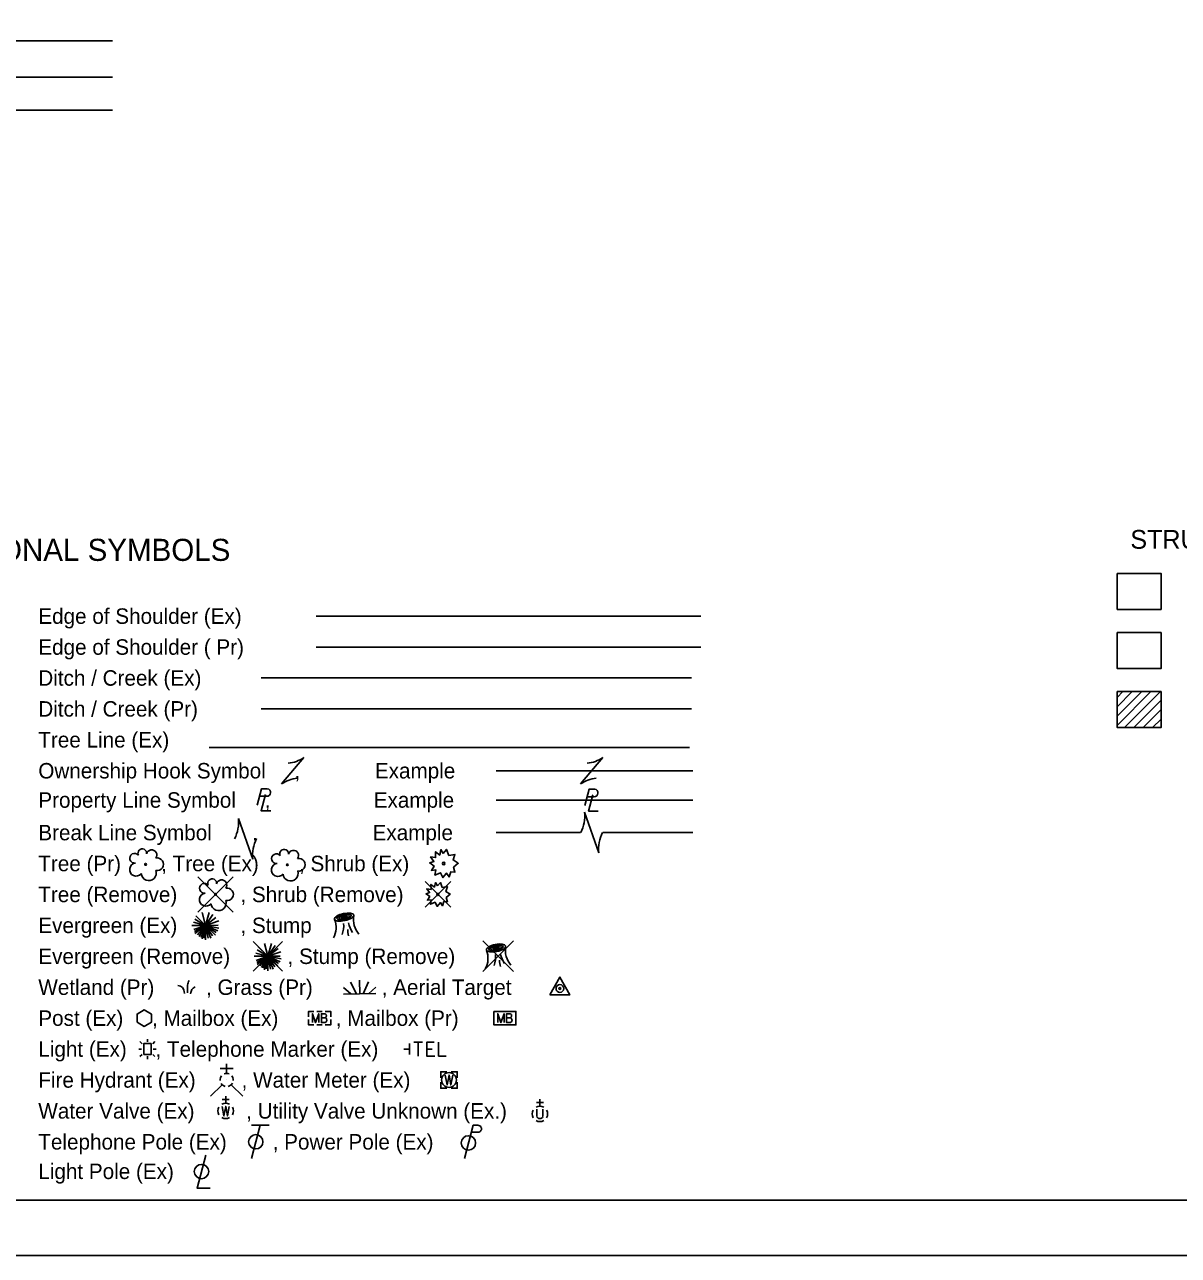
# Model space of a CAD drawing. Extents: x 63.4 to 97.4, y 0.4 to 22.4.
# Drawn here: x 71.41 to 81.86, y 0.42 to 11.56 of the extents above; entities that cross this region are included whole.
import ezdxf

# ---------------------------------------------------------------- set-up
doc = ezdxf.new("R2010")
doc.units = 0
for name, color, linetype in [('Default', 7, 'Continuous'), ('SC_Shading1', 7, 'Continuous'), ('SH_Border', 7, 'Continuous'), ('SH_Cut_Line', 7, 'Continuous'), ('SH_Data', 7, 'Continuous'), ('SH_Text', 7, 'Continuous')]:
    doc.layers.add(name, color=color, linetype=linetype)

msp = doc.modelspace()

# ---------------------------------------------------------------- linework, layer by layer
at = {"layer": 'Default'}
msp.add_lwpolyline([(81.311, 6.059), (81.708, 6.059), (81.708, 5.733), (81.311, 5.733)], close=True, dxfattribs=at)
at = {"layer": 'SC_Shading1'}
msp.add_lwpolyline([(81.311, 5.733), (81.708, 5.733), (81.708, 6.059), (81.311, 6.059)], close=True, dxfattribs=at)
at = {"layer": 'SH_Border'}
msp.add_lwpolyline([(64.912, 21.92), (96.912, 21.92), (96.912, 0.92), (64.912, 0.92)], close=True, dxfattribs=at)
at = {"layer": 'SH_Cut_Line'}
msp.add_lwpolyline([(63.412, 0.42), (97.412, 0.42), (97.412, 22.42), (63.412, 22.42)], close=True, dxfattribs=at)
at = {"layer": 'SH_Data'}
for p, q in [((72.209, 11.416), (70.959, 11.416)), ((72.209, 11.089), (70.959, 11.089)), ((72.209, 10.789), (70.959, 10.789))]:
    msp.add_line(p, q, dxfattribs=at)
at = {"layer": 'SH_Text'}
for p, q in [((74.055, 6.208), (77.538, 6.208)), ((74.055, 5.928), (77.538, 5.928)), ((73.555, 5.648), (77.455, 5.648)), ((81.311, 5.522), (81.312, 5.524)), ((81.311, 5.472), (81.362, 5.524)), ((81.311, 5.387), (81.447, 5.524)), ((81.311, 5.303), (81.532, 5.524)), ((81.311, 5.218), (81.616, 5.524)), ((81.375, 5.198), (81.701, 5.524)), ((73.555, 5.368), (77.455, 5.368)), ((81.46, 5.198), (81.708, 5.446)), ((81.545, 5.198), (81.708, 5.361)), ((81.629, 5.198), (81.708, 5.276)), ((81.311, 5.202), (81.315, 5.198)), ((73.087, 5.018), (77.437, 5.018)), ((73.742, 4.688), (73.942, 4.928)), ((76.45, 4.688), (76.65, 4.928)), ((73.842, 4.808), (73.842, 4.808)), ((75.685, 4.808), (77.467, 4.808)), ((76.55, 4.808), (76.55, 4.808)), ((73.542, 4.577), (73.607, 4.577)), ((76.508, 4.573), (76.573, 4.573)), ((73.582, 4.546), (73.582, 4.546)), ((75.685, 4.543), (77.467, 4.543)), ((76.548, 4.542), (76.548, 4.542)), ((73.35, 4.376), (73.48, 4.008)), ((76.485, 4.432), (76.615, 4.064)), ((75.685, 4.248), (76.45, 4.248)), ((76.55, 4.248), (76.55, 4.248)), ((76.65, 4.248), (77.467, 4.248)), ((73.415, 4.192), (73.415, 4.192)), ((72.982, 3.848), (73.303, 3.527)), ((73.303, 3.848), (72.982, 3.527)), ((75.042, 3.804), (75.273, 3.572)), ((75.273, 3.804), (75.042, 3.572)), ((73.143, 3.688), (73.143, 3.688)), ((75.157, 3.688), (75.157, 3.688)), ((73.053, 3.408), (72.956, 3.465)), ((73.053, 3.408), (72.966, 3.495)), ((73.053, 3.408), (73.022, 3.523)), ((73.053, 3.408), (73.085, 3.525)), ((73.053, 3.408), (73.12, 3.505)), ((73.053, 3.408), (73.145, 3.478)), ((72.93, 3.408), (73.053, 3.408)), ((73.053, 3.408), (72.943, 3.437)), ((73.053, 3.408), (72.946, 3.369)), ((73.053, 3.408), (72.954, 3.351)), ((73.053, 3.408), (72.956, 3.333)), ((73.053, 3.408), (72.98, 3.321)), ((73.053, 3.408), (72.995, 3.307)), ((73.053, 3.408), (73.012, 3.299)), ((73.053, 3.408), (73.022, 3.286)), ((73.053, 3.408), (73.04, 3.293)), ((73.053, 3.408), (73.172, 3.448)), ((73.053, 3.408), (73.166, 3.41)), ((73.053, 3.277), (73.053, 3.408)), ((73.053, 3.408), (73.076, 3.292)), ((73.053, 3.408), (73.102, 3.291)), ((73.053, 3.408), (73.117, 3.313)), ((73.053, 3.408), (73.143, 3.32)), ((73.053, 3.408), (73.149, 3.344)), ((73.053, 3.408), (73.165, 3.359)), ((73.053, 3.408), (73.174, 3.384)), ((74.327, 3.408), (74.327, 3.408)), ((73.484, 3.261), (73.751, 2.994)), ((73.751, 3.261), (73.484, 2.994)), ((73.617, 3.128), (73.586, 3.243)), ((73.617, 3.128), (73.649, 3.245)), ((75.563, 3.267), (75.842, 2.989)), ((75.842, 3.267), (75.563, 2.989)), ((73.494, 3.128), (73.617, 3.128)), ((73.617, 3.128), (73.507, 3.157)), ((73.617, 3.128), (73.51, 3.089)), ((73.617, 3.128), (73.518, 3.071)), ((73.617, 3.128), (73.52, 3.185)), ((73.617, 3.128), (73.52, 3.053)), ((73.617, 3.128), (73.53, 3.215)), ((73.617, 3.128), (73.544, 3.041)), ((73.617, 3.128), (73.559, 3.027)), ((73.617, 3.128), (73.576, 3.019)), ((73.617, 3.128), (73.586, 3.006)), ((73.617, 3.128), (73.604, 3.013)), ((73.617, 3.128), (73.684, 3.225)), ((73.617, 3.128), (73.709, 3.198)), ((73.617, 3.128), (73.736, 3.168)), ((73.617, 3.128), (73.73, 3.13)), ((73.617, 2.997), (73.617, 3.128)), ((73.617, 3.128), (73.64, 3.012)), ((73.617, 3.128), (73.666, 3.011)), ((73.617, 3.128), (73.681, 3.033)), ((73.617, 3.128), (73.707, 3.04)), ((73.617, 3.128), (73.713, 3.064)), ((73.617, 3.128), (73.729, 3.079)), ((73.617, 3.128), (73.738, 3.104)), ((73.617, 3.128), (73.617, 3.128)), ((75.702, 3.128), (75.702, 3.128)), ((75.703, 3.128), (75.703, 3.128)), ((74.449, 2.788), (74.447, 2.913)), ((74.37, 2.787), (74.302, 2.844)), ((74.303, 2.786), (74.595, 2.79)), ((74.419, 2.787), (74.367, 2.893)), ((74.479, 2.788), (74.528, 2.896)), ((74.528, 2.789), (74.594, 2.848)), ((74.06, 2.629), (74.11, 2.629)), ((74.086, 2.568), (74.086, 2.568)), ((75.764, 2.568), (75.764, 2.568)), ((74.06, 2.507), (74.11, 2.507)), ((72.478, 2.336), (72.459, 2.355)), ((72.526, 2.352), (72.526, 2.378)), ((72.593, 2.355), (72.574, 2.336)), ((72.474, 2.288), (72.447, 2.288)), ((72.478, 2.239), (72.459, 2.221)), ((72.526, 2.288), (72.526, 2.288)), ((72.593, 2.221), (72.574, 2.239)), ((72.605, 2.288), (72.578, 2.288)), ((74.899, 2.288), (74.849, 2.288)), ((74.899, 2.238), (74.899, 2.338)), ((72.526, 2.224), (72.526, 2.197)), ((73.244, 2.068), (73.244, 2.154)), ((73.304, 2.111), (73.184, 2.111)), ((73.244, 2.008), (73.244, 2.008)), ((73.244, 2.008), (73.244, 2.008)), ((75.258, 2.008), (75.258, 2.008)), ((73.202, 1.965), (73.098, 1.861)), ((73.286, 1.965), (73.39, 1.861)), ((73.267, 1.83), (73.203, 1.83)), ((73.235, 1.798), (73.235, 1.861)), ((76.113, 1.803), (76.049, 1.803)), ((76.081, 1.771), (76.081, 1.835)), ((73.235, 1.728), (73.235, 1.728)), ((76.054, 1.745), (76.054, 1.676)), ((76.081, 1.701), (76.081, 1.701)), ((76.108, 1.745), (76.108, 1.676)), ((73.628, 1.598), (73.468, 1.598)), ((73.548, 1.598), (73.468, 1.298)), ((75.477, 1.598), (75.397, 1.298)), ((75.477, 1.598), (75.519, 1.598)), ((75.46, 1.534), (75.519, 1.534))]:
    msp.add_line(p, q, dxfattribs=at)
for points in [[(81.311, 6.594), (81.708, 6.594), (81.708, 6.268), (81.311, 6.268)], [(81.311, 5.524), (81.708, 5.524), (81.708, 5.198), (81.311, 5.198)], [(76.172, 2.778), (76.352, 2.778), (76.262, 2.939)], [(75.664, 2.629), (75.864, 2.629), (75.864, 2.507), (75.664, 2.507)], [(72.493, 2.238), (72.559, 2.238), (72.559, 2.338), (72.493, 2.338)]]:
    msp.add_lwpolyline(points, close=True, dxfattribs=at)
for points in [[(73.521, 4.497), (73.56, 4.645), (73.612, 4.645)], [(73.596, 4.594), (73.556, 4.446), (73.643, 4.446)], [(76.487, 4.493), (76.526, 4.641), (76.578, 4.641)], [(76.561, 4.59), (76.522, 4.442), (76.609, 4.442)], [(75.206, 4.058), (75.236, 4.095), (75.257, 4.042), (75.312, 4.051), (75.295, 4.001), (75.342, 3.971), (75.299, 3.934), (75.312, 3.889), (75.274, 3.892), (75.258, 3.846), (75.236, 3.881), (75.202, 3.84), (75.181, 3.884), (75.13, 3.863), (75.14, 3.91), (75.099, 3.906), (75.123, 3.945), (75.084, 3.974), (75.121, 3.987), (75.091, 4.027), (75.137, 4.022), (75.136, 4.074), (75.174, 4.045), (75.184, 4.094), (75.206, 4.058)], [(75.154, 3.765), (75.18, 3.796), (75.197, 3.751), (75.244, 3.759), (75.229, 3.716), (75.269, 3.691), (75.233, 3.659), (75.244, 3.621), (75.212, 3.623), (75.198, 3.585), (75.18, 3.614), (75.151, 3.579), (75.132, 3.617), (75.089, 3.599), (75.097, 3.639), (75.063, 3.635), (75.083, 3.669), (75.05, 3.693), (75.082, 3.704), (75.056, 3.738), (75.095, 3.734), (75.094, 3.778), (75.126, 3.754), (75.135, 3.795), (75.154, 3.765)], [(72.433, 2.53), (72.498, 2.493), (72.563, 2.53), (72.563, 2.605), (72.498, 2.643), (72.433, 2.605), (72.433, 2.53)], [(73.986, 2.58), (73.986, 2.629), (74.034, 2.629)], [(74.021, 2.528), (74.021, 2.608), (74.05, 2.528), (74.078, 2.608), (74.078, 2.528)], [(74.137, 2.571), (74.14, 2.574), (74.142, 2.576), (74.143, 2.578), (74.144, 2.579), (74.145, 2.582), (74.146, 2.584), (74.147, 2.588), (74.147, 2.59), (74.147, 2.593), (74.146, 2.596), (74.145, 2.6), (74.143, 2.602), (74.14, 2.605), (74.137, 2.606), (74.136, 2.607), (74.133, 2.608), (74.102, 2.608), (74.102, 2.528), (74.137, 2.528), (74.141, 2.53), (74.145, 2.533), (74.148, 2.539), (74.15, 2.544), (74.151, 2.55), (74.151, 2.554), (74.149, 2.557), (74.147, 2.563), (74.144, 2.567), (74.137, 2.571), (74.102, 2.571)], [(74.136, 2.629), (74.186, 2.629), (74.186, 2.58)], [(75.699, 2.528), (75.699, 2.608), (75.728, 2.528), (75.756, 2.608), (75.756, 2.528)], [(75.815, 2.571), (75.818, 2.574), (75.82, 2.576), (75.821, 2.578), (75.822, 2.579), (75.823, 2.582), (75.824, 2.584), (75.825, 2.588), (75.825, 2.59), (75.825, 2.593), (75.824, 2.596), (75.823, 2.6), (75.821, 2.602), (75.818, 2.605), (75.815, 2.606), (75.814, 2.607), (75.811, 2.608), (75.78, 2.608), (75.78, 2.528), (75.815, 2.528), (75.819, 2.53), (75.823, 2.533), (75.826, 2.539), (75.828, 2.544), (75.829, 2.55), (75.829, 2.554), (75.827, 2.557), (75.825, 2.563), (75.822, 2.567), (75.815, 2.571), (75.78, 2.571)], [(74.034, 2.507), (73.986, 2.507), (73.986, 2.555)], [(74.186, 2.555), (74.186, 2.507), (74.136, 2.507)], [(74.939, 2.35), (75.017, 2.35)], [(74.979, 2.35), (74.979, 2.225)], [(75.124, 2.35), (75.057, 2.35), (75.057, 2.225), (75.129, 2.225)], [(75.164, 2.35), (75.164, 2.225), (75.232, 2.225)], [(75.057, 2.288), (75.105, 2.288)], [(75.238, 2.083), (75.183, 2.083), (75.183, 2.028)], [(75.224, 2.053), (75.241, 1.963), (75.258, 2.053), (75.274, 1.963), (75.291, 2.053)], [(75.333, 2.028), (75.333, 2.083), (75.278, 2.083)], [(75.183, 1.988), (75.183, 1.933), (75.238, 1.933)], [(75.278, 1.933), (75.333, 1.933), (75.333, 1.988)], [(73.203, 1.769), (73.219, 1.683), (73.235, 1.769), (73.251, 1.683), (73.267, 1.769)], [(73.055, 1.327), (72.976, 1.027), (73.095, 1.027)]]:
    msp.add_lwpolyline(points, dxfattribs=at)
for centre, radius in [((72.51, 3.96), 0.0084), ((73.794, 3.956), 0.0072), ((75.21, 3.968), 0.0115), ((73.143, 3.688), 0.0072), ((75.157, 3.688), 0.00979), ((76.262, 2.836), 0.035), ((76.262, 2.836), 0.008), ((75.258, 2.008), 0.0675), ((73.508, 1.448), 0.065), ((75.434, 1.438), 0.065), ((73.016, 1.179), 0.065)]:
    msp.add_circle(centre, radius, dxfattribs=at)
for centre, radius, start, end in [((73.784, 5.143), 0.267, 273.6945, 306.337), ((76.492, 5.143), 0.267, 273.6945, 306.337), ((73.9, 4.473), 0.267, 93.6945, 126.337), ((76.608, 4.473), 0.267, 93.6945, 126.337), ((73.607, 4.611), 0.0345, 270.471, 81.3281), ((76.572, 4.607), 0.0345, 270.471, 81.3281), ((73.018, 4.344), 0.334, 332.9422, 5.5848), ((76.153, 4.4), 0.334, 332.9422, 5.5848), ((76.947, 4.096), 0.334, 152.9422, 185.5848), ((73.812, 4.041), 0.334, 152.9422, 185.5848), ((72.41, 4.016), 0.0441, 39.0625, 279.5412), ((72.48, 4.061), 0.0395, 354.0047, 205.9741), ((72.565, 4.045), 0.0466, 323.83, 165.0376), ((72.614, 3.961), 0.0574, 259.1453, 101.4596), ((73.695, 4.012), 0.0441, 39.0625, 279.5412), ((73.765, 4.057), 0.0395, 354.0047, 205.9741), ((73.849, 4.041), 0.0466, 323.83, 165.0376), ((73.898, 3.957), 0.0574, 259.1453, 101.4596), ((72.424, 3.913), 0.0592, 96.1722, 320.5737), ((72.538, 3.882), 0.0685, 184.9476, 19.4572), ((73.709, 3.91), 0.0592, 96.1722, 320.5737), ((73.823, 3.878), 0.0685, 184.9476, 19.4572), ((73.113, 3.789), 0.0395, 354.0047, 205.9741), ((73.198, 3.773), 0.0466, 323.83, 165.0376), ((73.057, 3.641), 0.0592, 96.1722, 320.5737), ((73.043, 3.744), 0.0441, 39.0625, 279.5412), ((73.247, 3.689), 0.0574, 259.1453, 101.4596), ((73.171, 3.61), 0.0685, 184.9476, 19.4572), ((74.035, 3.39), 0.2, 331.5338, 20.9269), ((74.607, 3.465), 0.215, 171.4106, 219.9194), ((74.051, 3.409), 0.253, 340.7938, 3.5481), ((74.522, 3.368), 0.182, 178.7926, 197.1224), ((74.652, 3.511), 0.316, 194.9653, 212.1216), ((75.411, 3.11), 0.2, 331.5338, 20.9269), ((75.427, 3.129), 0.253, 340.7938, 3.5481), ((76.028, 3.231), 0.316, 194.9653, 212.1216), ((75.983, 3.185), 0.215, 171.4106, 219.9194), ((75.898, 3.088), 0.182, 178.7926, 197.1224), ((73.244, 2.008), 0.06, 140.021, 184.0629), ((73.244, 2.008), 0.06, 68.1395, 112.038), ((73.244, 2.008), 0.06, 356.0165, 39.9889), ((73.244, 2.008), 0.06, 211.8788, 255.8479), ((73.244, 2.008), 0.06, 283.8239, 329.9097), ((73.235, 1.728), 0.07, 60.0184, 120.0157), ((73.235, 1.728), 0.07, 150.0184, 209.9816), ((73.235, 1.728), 0.07, 330.0184, 29.9816), ((76.081, 1.701), 0.07, 150.0184, 209.9816), ((76.081, 1.701), 0.07, 60.0184, 120.0157), ((76.081, 1.688), 0.03, 205.1924, 334.8076), ((76.081, 1.701), 0.07, 330.0184, 29.9816), ((73.235, 1.728), 0.07, 239.9843, 299.9816), ((75.52, 1.566), 0.0319, 268.8767, 91.1233), ((76.081, 1.701), 0.07, 239.9843, 299.9816)]:
    msp.add_arc(centre, radius, start, end, dxfattribs=at)
for centre, major_axis in [((74.308, 3.483), (0.0868, 0.0187)), ((74.308, 3.483), (0.0651, 0.0141)), ((74.308, 3.483), (0.0488, 0.0105)), ((74.308, 3.483), (0.0275, 0.0059)), ((74.308, 3.483), (0.0154, 0.0033)), ((75.684, 3.203), (0.0868, 0.0187)), ((75.684, 3.203), (0.0651, 0.0141)), ((75.684, 3.203), (0.0488, 0.0105)), ((75.684, 3.203), (0.0275, 0.0059)), ((75.684, 3.203), (0.0154, 0.0033))]:
    msp.add_ellipse(centre, major_axis=major_axis, ratio=0.36865, dxfattribs=at)
for points in [[(72.889, 2.796), (72.889, 2.844), (72.895, 2.888), (72.904, 2.909)], [(72.802, 2.863), (72.843, 2.846), (72.861, 2.792)], [(72.917, 2.789), (72.929, 2.828), (72.958, 2.851)]]:
    msp.add_spline(points, degree=3, dxfattribs=at)

# ---------------------------------------------------------------- texts
for s, height, p in [('CONVENTIONAL SYMBOLS', 0.2, (69.8, 6.708)), ('STRUCTURE KEY', 0.17, (81.429, 6.818)), ('Edge of Shoulder (Ex)', 0.14, (71.538, 6.138)), ('Edge of Shoulder ( Pr)', 0.14, (71.538, 5.858)), ('Ditch / Creek (Ex)', 0.14, (71.538, 5.578)), ('Ditch / Creek (Pr)', 0.14, (71.538, 5.298)), ('Tree Line (Ex)', 0.14, (71.538, 5.018)), ('Ownership Hook Symbol     ,             Example', 0.14, (71.538, 4.738)), ('Property Line Symbol     ,                  Example', 0.14, (71.538, 4.473)), ('Break Line Symbol       ,                    Example', 0.14, (71.538, 4.178)), ('Tree (Pr)       , Tree (Ex)       , Shrub (Ex)', 0.14, (71.538, 3.898)), ('Tree (Remove)           , Shrub (Remove)', 0.14, (71.538, 3.618)), ('Evergreen (Ex)           , Stump ', 0.14, (71.538, 3.338)), ('Evergreen (Remove)          , Stump (Remove)', 0.14, (71.538, 3.058)), ('Wetland (Pr)         , Grass (Pr)            , Aerial Target    ', 0.14, (71.538, 2.778)), ('Post (Ex)     , Mailbox (Ex)          , Mailbox (Pr)', 0.14, (71.538, 2.498)), ('Light (Ex)     , Telephone Marker (Ex)     ', 0.14, (71.538, 2.218)), ('Fire Hydrant (Ex)        , Water Meter (Ex)', 0.14, (71.538, 1.938)), ('Water Valve (Ex)         , Utility Valve Unknown (Ex.)', 0.14, (71.538, 1.658)), ('Telephone Pole (Ex)        , Power Pole (Ex)', 0.14, (71.538, 1.378)), ('Light Pole (Ex)     ', 0.14, (71.538, 1.111))]:
    msp.add_text(s, height=height, dxfattribs=at).set_placement(p)

doc.saveas('drawing.dxf')
